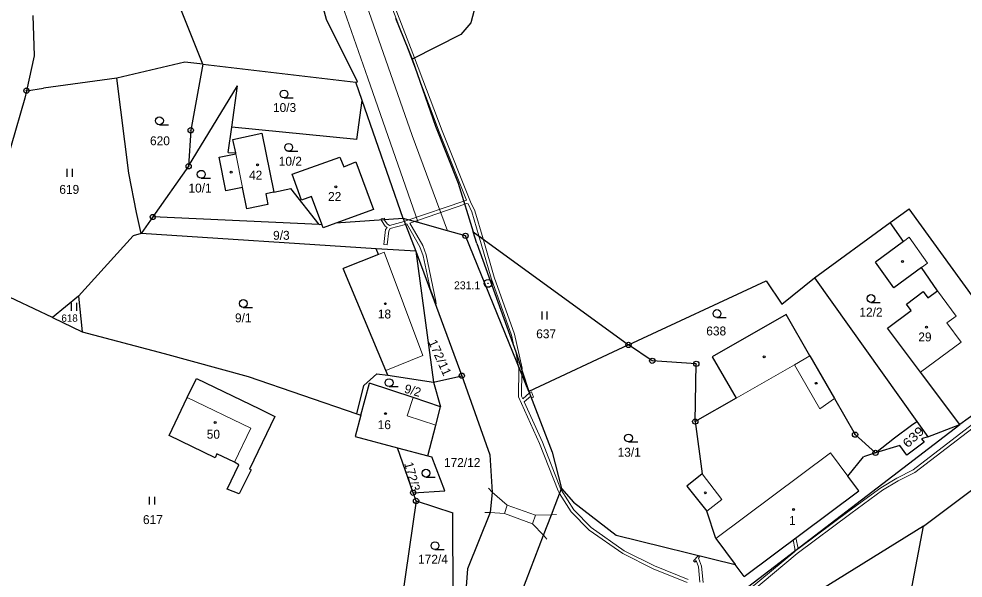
# Model space of a CAD drawing. Extents: x -653193 to -651624, y -1092017 to -1090260.
# Drawn here: x -653007.1 to -652826.7, y -1091249.7 to -1091143 of the extents above; entities that cross this region are included whole.
import ezdxf
from ezdxf.enums import TextEntityAlignment as Align

# ---------------------------------------------------------------- set-up
doc = ezdxf.new("R2010")
doc.units = 0
doc.header["$LTSCALE"] = 0.68
for name, color, linetype, lineweight in [('1', 7, 'Continuous', 25), ('13', 7, 'Continuous', 13), ('3', 7, 'Continuous', 25), ('4', 7, 'Continuous', 13), ('5', 7, 'Continuous', 25), ('8', 7, 'Continuous', 25)]:
    doc.layers.add(name, color=color, linetype=linetype, lineweight=lineweight)
doc.layers.add('2', color=7, linetype='Continuous')

msp = doc.modelspace()

# ---------------------------------------------------------------- linework, layer by layer
at = {"layer": '1'}
for p, q in [((-652948.33, -1091143.08), (-652953.97, -1091122.11)), ((-652917.65, -1091132.22), (-652920.79, -1091143.71)), ((-652971.95, -1091151.58), (-652978.03, -1091136.35)), ((-653004.4, -1091142.31), (-653004.16, -1091149.98)), ((-652942.39, -1091155), (-652948.33, -1091143.08)), ((-652935.16, -1091142.84), (-652931.98, -1091150.63)), ((-652920.79, -1091143.71), (-652922.69, -1091145.94)), ((-652922.69, -1091145.94), (-652931.98, -1091150.63)), ((-653004.16, -1091149.98), (-653005.63, -1091156.67)), ((-652975.4, -1091151.22), (-652988.37, -1091154.27)), ((-652971.95, -1091151.58), (-652975.4, -1091151.22)), ((-652931.98, -1091150.63), (-652927.52, -1091163.44)), ((-652971.95, -1091151.58), (-652974.25, -1091164.22)), ((-652971.95, -1091151.58), (-652942.72, -1091155.02)), ((-652988.37, -1091154.27), (-653002.37, -1091156.21)), ((-652986.09, -1091172.39), (-652988.37, -1091154.27)), ((-652942.72, -1091155.02), (-652942.39, -1091155)), ((-653005.63, -1091156.67), (-653005.94, -1091158.08)), ((-653005.63, -1091156.67), (-653002.37, -1091156.21)), ((-652974.65, -1091171.1), (-652965.35, -1091155.73)), ((-652966.42, -1091163.61), (-652965.35, -1091155.73)), ((-653005.94, -1091158.08), (-653016, -1091192.75)), ((-652933.68, -1091181.04), (-652941.49, -1091158.56)), ((-652967.08, -1091168.49), (-652966.42, -1091163.61)), ((-652942.53, -1091165.96), (-652966.42, -1091163.61)), ((-652927.52, -1091163.44), (-652923.19, -1091174.3)), ((-652974.25, -1091164.22), (-652974.65, -1091171.1)), ((-652966.18, -1091165.97), (-652960.69, -1091164.8)), ((-652960.69, -1091164.8), (-652958.37, -1091176.05)), ((-652965.66, -1091168.53), (-652966.18, -1091165.97)), ((-652968.8, -1091169.38), (-652965.62, -1091168.74)), ((-652967.54, -1091175.77), (-652968.8, -1091169.38)), ((-652967.08, -1091168.49), (-652965.66, -1091168.53)), ((-652965.62, -1091168.74), (-652965.66, -1091168.53)), ((-652954.85, -1091172.63), (-652945.75, -1091169.36)), ((-652945.75, -1091169.36), (-652945.01, -1091171.19)), ((-652974.65, -1091171.1), (-652981.5, -1091180.77)), ((-652945.01, -1091171.19), (-652942.69, -1091170.26)), ((-652942.69, -1091170.26), (-652939.35, -1091179.32)), ((-652984.58, -1091179.89), (-652986.09, -1091172.39)), ((-652953.07, -1091177.57), (-652954.85, -1091172.63)), ((-652923.19, -1091174.3), (-652920.29, -1091183.6)), ((-652964.34, -1091175.13), (-652967.54, -1091175.77)), ((-652963.53, -1091179.25), (-652964.34, -1091175.13)), ((-652958.37, -1091176.05), (-652959.93, -1091176.38)), ((-652959.93, -1091176.38), (-652959.5, -1091178.42)), ((-652958.37, -1091176.05), (-652955.14, -1091175.32)), ((-652949.72, -1091182.2), (-652955.14, -1091175.32)), ((-652959.5, -1091178.42), (-652963.53, -1091179.25)), ((-652951.17, -1091176.87), (-652953.07, -1091177.57)), ((-652949.19, -1091182.16), (-652951.17, -1091176.87)), ((-652983.72, -1091183.91), (-652984.58, -1091179.89)), ((-652939.35, -1091179.32), (-652946.56, -1091181.98)), ((-652840.66, -1091181.84), (-652837.06, -1091179.21)), ((-652814.18, -1091210.82), (-652837.06, -1091179.21)), ((-652981.5, -1091180.77), (-652983.72, -1091183.91)), ((-652949.72, -1091182.2), (-652981.5, -1091180.77)), ((-652946.56, -1091181.98), (-652948.93, -1091182.85)), ((-652933.68, -1091181.04), (-652946.56, -1091181.98)), ((-652933.68, -1091181.04), (-652931.27, -1091187.33)), ((-652930.82, -1091181.84), (-652933.68, -1091181.04)), ((-652925.23, -1091183.4), (-652930.82, -1091181.84)), ((-652855.14, -1091192.41), (-652840.66, -1091181.84)), ((-652838.15, -1091185.43), (-652840.66, -1091181.84)), ((-652983.72, -1091183.91), (-652985.25, -1091184.38)), ((-652938.83, -1091186.84), (-652983.72, -1091183.91)), ((-652949.72, -1091182.2), (-652949.19, -1091182.16)), ((-652948.93, -1091182.85), (-652949.19, -1091182.16)), ((-652919.59, -1091185.84), (-652920.29, -1091183.6)), ((-652920.29, -1091183.6), (-652890.64, -1091205.2)), ((-652985.25, -1091184.38), (-652995.67, -1091195.92)), ((-652838.15, -1091185.43), (-652843.5, -1091189.41)), ((-652938.42, -1091187.92), (-652938.83, -1091186.84)), ((-652931.27, -1091187.33), (-652938.83, -1091186.84)), ((-652931.27, -1091187.33), (-652922.49, -1091211.07)), ((-652931.27, -1091187.33), (-652927.9, -1091212.32)), ((-652919.59, -1091185.84), (-652912.16, -1091206.52)), ((-652938.42, -1091187.92), (-652945.17, -1091190.58)), ((-652936.98, -1091210.08), (-652945.17, -1091190.58)), ((-652839.98, -1091194.29), (-652843.5, -1091189.41)), ((-652834.68, -1091190.4), (-652839.98, -1091194.29)), ((-652831.66, -1091194.88), (-652834.68, -1091190.4)), ((-653000.66, -1091199.98), (-653016, -1091192.75)), ((-652861.34, -1091197.39), (-652855.14, -1091192.41)), ((-652855.14, -1091192.41), (-652835.58, -1091219.82)), ((-652890.64, -1091205.2), (-652864.38, -1091192.96)), ((-652864.38, -1091192.96), (-652861.34, -1091197.39)), ((-652995.67, -1091195.92), (-653000.66, -1091199.98)), ((-652995.67, -1091195.92), (-652994.97, -1091202.68)), ((-652837.55, -1091197.39), (-652834.37, -1091195.02)), ((-652834.37, -1091195.02), (-652833.47, -1091196.23)), ((-652833.47, -1091196.23), (-652831.66, -1091194.88)), ((-652836.65, -1091198.6), (-652837.55, -1091197.39)), ((-653000.66, -1091199.98), (-652994.97, -1091202.68)), ((-652860.56, -1091199.38), (-652874.64, -1091207.44)), ((-652856.01, -1091207.3), (-652860.56, -1091199.38)), ((-652841.17, -1091201.98), (-652836.65, -1091198.6)), ((-652994.97, -1091202.68), (-652979.31, -1091206.83)), ((-652834.89, -1091210.38), (-652841.17, -1091201.98)), ((-652890.64, -1091205.2), (-652909.68, -1091214.07)), ((-652979.31, -1091206.83), (-652963.29, -1091211.2)), ((-652912.16, -1091206.52), (-652909.68, -1091214.07)), ((-652856.01, -1091207.3), (-652851.33, -1091215.45)), ((-652877.9, -1091219.83), (-652877.7, -1091208.81)), ((-652874.64, -1091207.44), (-652870.1, -1091215.33)), ((-652941.2, -1091212.95), (-652938.73, -1091210.72)), ((-652938.73, -1091210.72), (-652936.62, -1091210.95)), ((-652936.62, -1091210.95), (-652936.98, -1091210.08)), ((-652936.62, -1091210.95), (-652927.9, -1091212.32)), ((-652827.4, -1091220.4), (-652834.89, -1091210.38)), ((-652814.18, -1091210.82), (-652827.4, -1091220.4)), ((-652974.91, -1091215.24), (-652973.15, -1091211.59)), ((-652973.15, -1091211.59), (-652961.13, -1091217.37)), ((-652963.29, -1091211.2), (-652942.55, -1091218.32)), ((-652941.77, -1091218.59), (-652940.12, -1091212.47)), ((-652931.79, -1091215.24), (-652940.12, -1091212.47)), ((-652927.9, -1091212.32), (-652922.49, -1091211.07)), ((-652927.9, -1091212.32), (-652926.54, -1091216.99)), ((-652922.49, -1091211.07), (-652917.11, -1091226.17)), ((-652942.55, -1091218.32), (-652941.2, -1091212.95)), ((-652909.68, -1091214.07), (-652905.23, -1091225.7)), ((-652978.37, -1091222.5), (-652974.91, -1091215.24)), ((-652926.54, -1091216.99), (-652931.79, -1091215.24)), ((-652870.1, -1091215.33), (-652877.9, -1091219.83)), ((-652851.33, -1091215.45), (-652847.38, -1091222.32)), ((-652927.47, -1091220.52), (-652926.54, -1091216.99)), ((-652941.77, -1091218.59), (-652942.86, -1091222.66)), ((-652942.55, -1091218.32), (-652941.77, -1091218.59)), ((-652877.9, -1091219.83), (-652876.58, -1091229.8)), ((-652836.59, -1091220.51), (-652835.58, -1091219.82)), ((-652835.58, -1091219.82), (-652833.49, -1091222.76)), ((-652834.31, -1091239.8), (-652807.67, -1091219.82)), ((-652928.97, -1091226.4), (-652927.47, -1091220.52)), ((-652868.72, -1091252.07), (-652827.4, -1091220.4)), ((-652839.84, -1091222.96), (-652836.59, -1091220.51)), ((-652833.49, -1091222.76), (-652827.4, -1091220.4)), ((-652969.59, -1091226.73), (-652978.37, -1091222.5)), ((-652942.86, -1091222.66), (-652934.76, -1091224.84)), ((-652843.48, -1091225.8), (-652847.38, -1091222.32)), ((-652843.48, -1091225.8), (-652839.84, -1091222.96)), ((-652833.49, -1091222.76), (-652834.67, -1091223.12)), ((-652834.67, -1091223.12), (-652834.21, -1091223.75)), ((-652931.76, -1091233.42), (-652934.76, -1091224.84)), ((-652934.76, -1091224.84), (-652928.97, -1091226.4)), ((-652838.81, -1091224.38), (-652843.48, -1091225.8)), ((-652837.47, -1091226.21), (-652838.81, -1091224.38)), ((-652834.21, -1091223.75), (-652837.47, -1091226.21)), ((-652969.24, -1091225.98), (-652969.59, -1091226.73)), ((-652965.92, -1091227.58), (-652969.24, -1091225.98)), ((-652928.97, -1091226.4), (-652928.23, -1091226.59)), ((-652925.71, -1091233.07), (-652928.23, -1091226.59)), ((-652917.11, -1091226.17), (-652916.7, -1091233.31)), ((-652905.23, -1091225.7), (-652903.42, -1091232.58)), ((-652848.76, -1091230.24), (-652845.74, -1091226.55)), ((-652843.48, -1091225.8), (-652845.74, -1091226.55)), ((-652967.29, -1091232.75), (-652965.08, -1091228.06)), ((-652965.08, -1091228.06), (-652965.92, -1091227.58)), ((-652963.01, -1091228.89), (-652962.74, -1091229.02)), ((-652962.74, -1091229.02), (-652964.98, -1091233.64)), ((-652876.58, -1091229.8), (-652879.53, -1091232.14)), ((-652846.66, -1091233.04), (-652848.76, -1091230.24)), ((-652905.37, -1091237.65), (-652903.42, -1091232.58)), ((-652903.42, -1091232.58), (-652901.16, -1091235.21)), ((-652879.53, -1091232.14), (-652875.66, -1091236.96)), ((-652964.98, -1091233.64), (-652967.29, -1091232.75)), ((-652931.76, -1091233.42), (-652925.71, -1091233.07)), ((-652931.22, -1091234.98), (-652931.76, -1091233.42)), ((-652916.7, -1091233.31), (-652917.08, -1091237.2)), ((-652868.57, -1091249.42), (-652846.66, -1091233.04)), ((-652931.22, -1091234.98), (-652934.04, -1091254.46)), ((-652931.22, -1091234.98), (-652924.17, -1091237.24)), ((-652901.16, -1091235.21), (-652893.03, -1091241.49)), ((-652924.16, -1091255.94), (-652924.17, -1091237.24)), ((-652917.08, -1091237.2), (-652921.38, -1091247.95)), ((-652906.87, -1091241.53), (-652905.37, -1091237.65)), ((-652873.94, -1091242.14), (-652875.66, -1091236.96)), ((-652834.31, -1091239.8), (-652855.74, -1091253.08)), ((-652837.4, -1091255.94), (-652834.31, -1091239.8)), ((-652911.02, -1091252.3), (-652906.87, -1091241.53)), ((-652893.03, -1091241.49), (-652870.28, -1091247.11)), ((-652873.94, -1091242.14), (-652870.28, -1091247.11)), ((-652921.38, -1091247.95), (-652922.24, -1091258.57)), ((-652868.57, -1091249.42), (-652870.28, -1091247.11))]:
    msp.add_line(p, q, dxfattribs=at)
for points in [[(-652942.53, -1091165.96), (-652941.49, -1091158.56), (-652942.72, -1091155.02)], [(-652909.68, -1091214.07), (-652921.78, -1091184.37), (-652925.23, -1091183.4)], [(-652877.7, -1091208.81), (-652886.11, -1091208.23), (-652890.64, -1091205.2)], [(-652961.13, -1091217.37), (-652958.18, -1091218.88), (-652963.01, -1091228.89)]]:
    msp.add_lwpolyline(points, dxfattribs=at)
at = {"layer": '13'}
for points in [[(-652937.22, -1091135.49), (-652942.85, -1091122.73), (-652943.01, -1091123.87), (-652937.78, -1091135.71), (-652933.58, -1091146.72), (-652931.98, -1091150.63), (-652931.53, -1091150.4)], [(-652933.58, -1091146.72), (-652930.91, -1091153.7), (-652931.98, -1091150.63)], [(-652931.98, -1091150.63), (-652930.91, -1091153.7), (-652926.78, -1091164.52), (-652921.59, -1091177.58), (-652922.11, -1091177.76), (-652921.93, -1091178.33), (-652921.64, -1091178.23), (-652921.3, -1091178.28), (-652920.55, -1091179.79), (-652919.23, -1091184.37), (-652918.43, -1091184.95), (-652919.99, -1091179.57), (-652920.83, -1091177.89), (-652926.22, -1091164.3), (-652931.53, -1091150.4)], [(-652922.11, -1091177.76), (-652932.95, -1091181.47), (-652933.46, -1091181.61), (-652933.24, -1091182.18), (-652933, -1091182.11), (-652930.48, -1091186.48), (-652929.87, -1091188.16), (-652928.55, -1091194.41), (-652927.4, -1091197.4), (-652927.42, -1091196.82), (-652929.29, -1091188), (-652929.94, -1091186.22), (-652932.42, -1091181.93), (-652921.93, -1091178.33)], [(-652937.88, -1091181.11), (-652937.85, -1091181.34), (-652937.23, -1091181.3), (-652937.27, -1091181.03)], [(-652937.85, -1091181.34), (-652937.83, -1091181.46), (-652937.15, -1091182.52), (-652936.76, -1091182.8), (-652937.03, -1091183.19), (-652937.36, -1091186.04), (-652936.76, -1091186.1), (-652936.45, -1091183.41), (-652936.16, -1091182.98), (-652933.24, -1091182.18), (-652933.46, -1091181.61), (-652936.28, -1091182.39), (-652936.71, -1091182.1), (-652937.22, -1091181.38), (-652937.23, -1091181.3)], [(-652916.9, -1091192.44), (-652912.98, -1091203.33), (-652912.46, -1091205.68), (-652912.16, -1091206.52), (-652910.99, -1091210.09), (-652910.98, -1091209.62), (-652912.4, -1091203.17), (-652916.32, -1091192.26), (-652918.43, -1091184.95), (-652919.23, -1091184.37)], [(-652911.58, -1091209.68), (-652911.68, -1091215.08), (-652907.66, -1091224.03), (-652904.1, -1091233.08), (-652903.8, -1091233.56), (-652903.53, -1091232.85), (-652903.56, -1091232.8), (-652907.1, -1091223.79), (-652910.57, -1091216.09), (-652909.33, -1091214.98), (-652909.57, -1091214.36), (-652910.83, -1091215.51), (-652911.08, -1091214.96), (-652910.99, -1091210.09), (-652912.16, -1091206.52)], [(-652908.81, -1091215.14), (-652909.17, -1091214.16), (-652909.51, -1091214.3), (-652909.57, -1091214.36), (-652909.33, -1091214.98), (-652909.28, -1091214.93), (-652909.15, -1091215.28)], [(-652858.89, -1091244.54), (-652858.25, -1091244.04), (-652858.68, -1091242.03), (-652859.21, -1091242.42), (-652858.86, -1091244.04)]]:
    msp.add_lwpolyline(points, close=True, dxfattribs=at)
for points in [[(-652823.27, -1091219.05), (-652836.27, -1091229.05), (-652839.41, -1091230.63), (-652842.45, -1091232.45), (-652848.52, -1091236.88), (-652858.23, -1091244.12), (-652858.25, -1091244.04), (-652858.89, -1091244.54), (-652858.9, -1091244.63), (-652867.79, -1091252.03)], [(-652867.48, -1091252.56), (-652858.42, -1091245.02), (-652848.16, -1091237.36), (-652842.11, -1091232.95), (-652839.13, -1091231.15), (-652835.95, -1091229.57), (-652822.91, -1091219.53)], [(-652879.24, -1091249.98), (-652885.7, -1091247.37), (-652891.45, -1091244.5), (-652897.75, -1091240.08), (-652901.12, -1091236.65), (-652903.53, -1091232.85), (-652903.8, -1091233.56), (-652901.6, -1091237.03), (-652898.13, -1091240.54), (-652891.75, -1091245.02), (-652885.94, -1091247.91), (-652879.42, -1091250.56)], [(-652876.42, -1091250.57), (-652876.69, -1091247.4), (-652877.28, -1091245.89), (-652877.08, -1091245.68), (-652877.35, -1091245.44), (-652878.26, -1091246.4), (-652877.99, -1091246.64), (-652877.74, -1091246.37), (-652877.29, -1091247.54), (-652877.04, -1091250.46)]]:
    msp.add_lwpolyline(points, dxfattribs=at)
at = {"layer": '3'}
for p, q in [((-652956.433, -1091158.05), (-652954.683, -1091158.05)), ((-652980.233, -1091163.16), (-652978.483, -1091163.16)), ((-652955.553, -1091168.24), (-652953.803, -1091168.24)), ((-652997.831, -1091173.09), (-652997.831, -1091171.59)), ((-652996.83, -1091173.09), (-652996.83, -1091171.59)), ((-652972.243, -1091173.37), (-652970.493, -1091173.37)), ((-652996.991, -1091198.68), (-652996.991, -1091197.18)), ((-652995.99, -1091198.68), (-652995.99, -1091197.18)), ((-652964.213, -1091198.04), (-652962.463, -1091198.04)), ((-652844.343, -1091197.08), (-652842.593, -1091197.08)), ((-652907.161, -1091200.34), (-652907.161, -1091198.84)), ((-652906.16, -1091200.34), (-652906.16, -1091198.84)), ((-652873.753, -1091199.96), (-652872.003, -1091199.96)), ((-652936.373, -1091213.16), (-652934.623, -1091213.16)), ((-652890.643, -1091223.72), (-652888.893, -1091223.72)), ((-652929.323, -1091230.43), (-652927.573, -1091230.43)), ((-652982.121, -1091235.69), (-652982.121, -1091234.19)), ((-652981.12, -1091235.69), (-652981.12, -1091234.19)), ((-652927.603, -1091244.27), (-652925.853, -1091244.27))]:
    msp.add_line(p, q, dxfattribs=at)
for centre in [(-652956.4329, -1091157.2998), (-652980.2329, -1091162.4098), (-652955.5529, -1091167.4898), (-652972.2429, -1091172.6198), (-652964.2129, -1091197.2898), (-652844.3429, -1091196.3298), (-652873.7529, -1091199.2098), (-652936.3729, -1091212.4098), (-652890.6429, -1091222.9698), (-652929.3229, -1091229.6798), (-652927.6029, -1091243.5198)]:
    msp.add_circle(centre, 0.75, dxfattribs=at)
at = {"layer": '4'}
for p, q in [((-652950.21, -1091126.37), (-652940.46, -1091154.27)), ((-652941.43, -1091138.03), (-652931.98, -1091165.22)), ((-652940.46, -1091154.27), (-652930.82, -1091181.84)), ((-652931.98, -1091165.22), (-652925.23, -1091183.4)), ((-652965.62, -1091168.74), (-652964.34, -1091175.13)), ((-652837.08, -1091184.64), (-652838.15, -1091185.43)), ((-652837.08, -1091184.64), (-652833.52, -1091189.58)), ((-652937.29, -1091187.48), (-652938.42, -1091187.92)), ((-652833.52, -1091189.58), (-652834.68, -1091190.4)), ((-652831.66, -1091194.88), (-652828.09, -1091199.68)), ((-652828.09, -1091199.68), (-652829.86, -1091201)), ((-652829.86, -1091201), (-652827.11, -1091204.67)), ((-652827.11, -1091204.67), (-652834.89, -1091210.38)), ((-652858.95, -1091208.98), (-652856.01, -1091207.3)), ((-652870.1, -1091215.33), (-652858.95, -1091208.98)), ((-652974.91, -1091215.24), (-652962.79, -1091221.07)), ((-652931.79, -1091215.24), (-652932.9, -1091218.76)), ((-652927.47, -1091220.52), (-652932.9, -1091218.76)), ((-652965.92, -1091227.58), (-652962.79, -1091221.07)), ((-652876.58, -1091229.8), (-652872.82, -1091234.69)), ((-652917.369, -1091232.566), (-652916.7, -1091233.309)), ((-652916.7, -1091233.31), (-652913.84, -1091235.79)), ((-652913.84, -1091235.79), (-652914.31, -1091237.37)), ((-652875.66, -1091236.96), (-652872.82, -1091234.69)), ((-652918.08, -1091237.199), (-652917.081, -1091237.199)), ((-652917.08, -1091237.2), (-652914.31, -1091237.37)), ((-652908.96, -1091239.36), (-652914.31, -1091237.37)), ((-652908.42, -1091237.68), (-652905.37, -1091237.65)), ((-652904.373, -1091237.563), (-652905.369, -1091237.651)), ((-652906.87, -1091241.53), (-652908.96, -1091239.36)), ((-652906.241, -1091242.308), (-652906.87, -1091241.531))]:
    msp.add_line(p, q, dxfattribs=at)
for points in [[(-652936.98, -1091210.08), (-652929.91, -1091207.21), (-652937.29, -1091187.48)], [(-652858.95, -1091208.98), (-652854.1, -1091217.42), (-652851.33, -1091215.45)], [(-652848.76, -1091230.24), (-652852.09, -1091225.79), (-652873.94, -1091242.14)], [(-652913.84, -1091235.79), (-652908.42, -1091237.68), (-652908.96, -1091239.36)]]:
    msp.add_lwpolyline(points, dxfattribs=at)
at = {"layer": '5'}
for centre in [(-652961.4768, -1091170.8292), (-652966.5368, -1091172.2092), (-652946.5368, -1091175.0192), (-652838.3268, -1091189.2692), (-652937.0868, -1091197.3292), (-652833.7468, -1091201.8192), (-652864.7268, -1091207.4592), (-652854.8168, -1091212.5192), (-652937.0468, -1091218.3092), (-652969.5768, -1091220.0092), (-652875.9768, -1091233.4292), (-652859.1168, -1091236.6292)]:
    msp.add_circle(centre, 0.175, dxfattribs=at)
at = {"layer": '8'}
for centre, radius in [((-653005.63, -1091156.6699), 0.5), ((-653005.63, -1091156.6699), 0.0303), ((-652974.25, -1091164.2199), 0.5), ((-652974.25, -1091164.2199), 0.0303), ((-652974.65, -1091171.0999), 0.5), ((-652974.65, -1091171.0999), 0.0303), ((-652981.5, -1091180.7699), 0.5), ((-652981.5, -1091180.7699), 0.0303), ((-652921.78, -1091184.3699), 0.5), ((-652921.78, -1091184.3699), 0.0303), ((-652917.46, -1091193.4498), 0.75), ((-652917.46, -1091193.4498), 0.03), ((-652890.64, -1091205.1999), 0.5), ((-652890.64, -1091205.1999), 0.0303), ((-652886.11, -1091208.2299), 0.5), ((-652886.11, -1091208.2299), 0.0303), ((-652877.7, -1091208.8099), 0.5), ((-652877.7, -1091208.8099), 0.0303), ((-652922.49, -1091211.0699), 0.5), ((-652922.49, -1091211.0699), 0.0303), ((-652877.9, -1091219.8299), 0.5), ((-652877.9, -1091219.8299), 0.0303), ((-652847.38, -1091222.3199), 0.5), ((-652847.38, -1091222.3199), 0.0303), ((-652843.48, -1091225.7999), 0.5), ((-652843.48, -1091225.7999), 0.0303), ((-652931.76, -1091233.4199), 0.5), ((-652931.76, -1091233.4199), 0.0303), ((-652931.22, -1091234.9799), 0.5), ((-652931.22, -1091234.9799), 0.0303)]:
    msp.add_circle(centre, radius, dxfattribs=at)

# ---------------------------------------------------------------- texts
at = {"layer": '2'}
for s, height, p in [('10/3', 1.7, (-652956.329, -1091160.735)), ('620', 1.7, (-652980.129, -1091167.075)), ('10/2', 1.7, (-652955.229, -1091170.985)), ('42', 1.7, (-652961.849, -1091173.625)), ('619', 1.7, (-652997.449, -1091176.355)), ('10/1', 1.7, (-652972.469, -1091176.105)), ('22', 1.7, (-652946.759, -1091177.705)), ('9/3', 1.7, (-652956.94, -1091185.125)), ('12/2', 1.7, (-652844.339, -1091199.785)), ('618', 1.4, (-652997.39, -1091200.78)), ('9/1', 1.7, (-652964.22, -1091200.885)), ('18', 1.7, (-652937.259, -1091200.145)), ('638', 1.7, (-652873.899, -1091203.385)), ('637', 1.7, (-652906.379, -1091203.925)), ('29', 1.7, (-652834.039, -1091204.525)), ('16', 1.7, (-652937.289, -1091221.275)), ('50', 1.7, (-652969.929, -1091223.095)), ('13/1', 1.7, (-652890.519, -1091226.535)), ('172/12', 1.7, (-652922.41, -1091228.495)), ('617', 1.7, (-652981.479, -1091239.395)), ('1', 1.7, (-652859.35, -1091239.545)), ('172/4', 1.7, (-652927.99, -1091246.955))]:
    msp.add_text(s, height=height, dxfattribs=at).set_placement(p, align=Align.CENTER)
for s, rotation, width, p in [('172/11', 294, 1.05, (-652927.4397, -1091207.9588)), ('639', 43, 1.2, (-652835.6747, -1091223.405))]:
    msp.add_text(s, height=1.7, rotation=rotation, dxfattribs=dict(at, width=width)).set_placement(p, align=Align.CENTER)
for s, rotation, p in [('9/2', 344, (-652932.0773, -1091214.7025)), ('172/3', 285, (-652932.7601, -1091230.551))]:
    msp.add_text(s, height=1.7, rotation=rotation, dxfattribs=at).set_placement(p, align=Align.CENTER)
at = {"layer": '8'}
msp.add_text('231.1', height=1.5, dxfattribs=at).set_placement((-652918.959, -1091194.567), align=Align.RIGHT)

doc.saveas('drawing.dxf')
